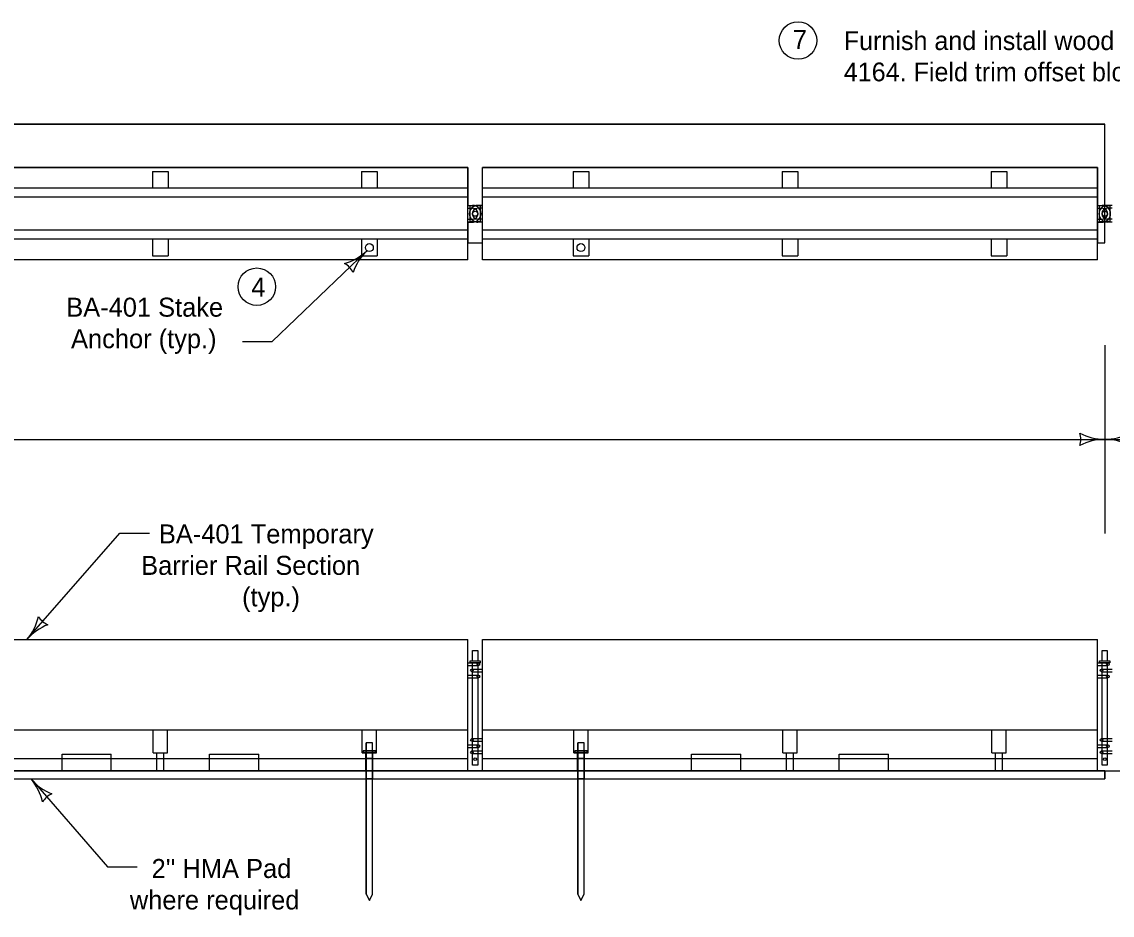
# Model space of a CAD drawing. Extents: x -2137026 to -2131464, y -2138478 to -2136524.
# Drawn here: x -2135538 to -2134666, y -2138230 to -2137516 of the extents above; entities that cross this region are included whole.
import ezdxf

# ---------------------------------------------------------------- set-up
doc = ezdxf.new("R2010")
doc.units = 0
for name, color, linetype in [('conPaving', 7, 'Continuous'), ('Level 2', 7, 'Continuous'), ('Level 3', 7, 'Continuous'), ('Level 41', 7, 'Continuous'), ('Level 9', 7, 'Continuous')]:
    doc.layers.add(name, color=color, linetype=linetype)

msp = doc.modelspace()

# ---------------------------------------------------------------- linework, layer by layer
at = {"layer": 'conPaving'}
for p, q in [((-2135592.12, -2138121.37), (-2135530.9, -2138121.37)), ((-2135530.9, -2138121.37), (-2135262.81, -2138121.37)), ((-2135348.82, -2138114.82), (-2135388.14, -2138114.82)), ((-2135262.81, -2138121.37), (-2135262.81, -2138114.82)), ((-2135257.89, -2138114.82), (-2135257.89, -2138121.37)), ((-2135257.89, -2138121.37), (-2135093.64, -2138121.37)), ((-2135093.64, -2138121.37), (-2135093.64, -2138114.82)), ((-2135088.73, -2138114.82), (-2135088.73, -2138121.37)), ((-2135088.73, -2138121.37), (-2134672.37, -2138121.37)), ((-2134884.74, -2138114.82), (-2134921.24, -2138114.82)), ((-2134672.37, -2138121.37), (-2134672.37, -2138114.82))]:
    msp.add_line(p, q, dxfattribs=at)
for points in [[(-2135430.3, -2138114.82), (-2135466.79, -2138114.82), (-2135506.11, -2138114.82), (-2135591.75, -2138114.82), (-2135592.12, -2138114.82)], [(-2135530.9, -2138121.37), (-2135530.9, -2138121.37)], [(-2135388.14, -2138114.82), (-2135424.63, -2138114.82), (-2135430.3, -2138114.82)], [(-2135262.81, -2138114.82), (-2135263.18, -2138114.82), (-2135348.82, -2138114.82)], [(-2135169.58, -2138114.82), (-2135181.95, -2138114.82), (-2135257.52, -2138114.82), (-2135257.89, -2138114.82)], [(-2135093.64, -2138114.82), (-2135094.01, -2138114.82), (-2135169.58, -2138114.82)], [(-2135002.71, -2138114.82), (-2135088.35, -2138114.82), (-2135088.73, -2138114.82)], [(-2134921.24, -2138114.82), (-2134926.9, -2138114.82), (-2134963.39, -2138114.82), (-2135002.71, -2138114.82)], [(-2134672.37, -2138114.82), (-2134678.55, -2138114.82), (-2134754.12, -2138114.82), (-2134759.78, -2138114.82), (-2134845.42, -2138114.82), (-2134884.74, -2138114.82)]]:
    msp.add_lwpolyline(points, dxfattribs=at)
msp.add_arc((-2135498.55, -2138093.81), 42.5, 220.43362, 220.43495, dxfattribs=at)
at = {"layer": 'Level 2'}
for p, q in [((-2135181.7, -2137632.29), (-2135673.22, -2137632.29)), ((-2135181.7, -2137706.01), (-2135181.7, -2137632.29)), ((-2134678.31, -2137632.29), (-2135169.83, -2137632.29)), ((-2135169.83, -2137706.01), (-2135169.83, -2137632.29)), ((-2134678.31, -2137706.01), (-2134678.31, -2137632.29)), ((-2135181.7, -2137648.67), (-2135673.22, -2137648.67)), ((-2134678.31, -2137648.67), (-2135169.83, -2137648.67)), ((-2135181.7, -2137656.04), (-2135673.22, -2137656.04)), ((-2134678.31, -2137656.04), (-2135169.83, -2137656.04)), ((-2135181.7, -2137682.26), (-2135673.22, -2137682.26)), ((-2134678.31, -2137682.26), (-2135169.83, -2137682.26)), ((-2135181.7, -2137689.63), (-2135673.22, -2137689.63)), ((-2134678.31, -2137689.63), (-2135169.83, -2137689.63)), ((-2135338.14, -2137771.44), (-2135262.36, -2137698.75)), ((-2135181.7, -2137706.01), (-2135673.22, -2137706.01)), ((-2134678.31, -2137706.01), (-2135169.83, -2137706.01)), ((-2135361.74, -2137771.44), (-2135338.14, -2137771.44)), ((-2134672.37, -2137774.34), (-2134672.37, -2137925.06)), ((-2135803.58, -2137849.7), (-2134672.37, -2137849.7)), ((-2134672.37, -2137849.7), (-2134532.49, -2137849.7)), ((-2135534.15, -2138009.96), (-2135459.86, -2137924.76)), ((-2135459.86, -2137924.76), (-2135436.26, -2137924.76)), ((-2135673.22, -2138009.96), (-2135181.7, -2138009.96)), ((-2135181.7, -2138114.57), (-2135181.7, -2138009.96)), ((-2135169.83, -2138114.57), (-2135169.83, -2138009.96)), ((-2135169.83, -2138009.96), (-2134678.31, -2138009.96)), ((-2134678.31, -2138114.57), (-2134678.31, -2138009.96)), ((-2135673.22, -2138082.05), (-2135181.7, -2138082.05)), ((-2135169.83, -2138082.05), (-2134678.31, -2138082.05)), ((-2135673.22, -2138104.99), (-2135181.7, -2138104.99)), ((-2135506.11, -2138101.71), (-2135466.79, -2138101.71)), ((-2135506.11, -2138114.82), (-2135506.11, -2138104.99)), ((-2135466.79, -2138114.82), (-2135466.79, -2138104.99)), ((-2135388.14, -2138101.71), (-2135348.82, -2138101.71)), ((-2135388.14, -2138114.82), (-2135388.14, -2138104.99)), ((-2135348.82, -2138114.82), (-2135348.82, -2138104.99)), ((-2135169.83, -2138104.99), (-2134678.31, -2138104.99)), ((-2135002.71, -2138101.71), (-2134963.39, -2138101.71)), ((-2135002.71, -2138114.82), (-2135002.71, -2138104.99)), ((-2134963.39, -2138114.82), (-2134963.39, -2138104.99)), ((-2134884.74, -2138101.71), (-2134845.42, -2138101.71)), ((-2134884.74, -2138114.82), (-2134884.74, -2138104.99)), ((-2134845.42, -2138114.82), (-2134845.42, -2138104.99)), ((-2135672.98, -2138114.82), (-2135506.11, -2138114.82)), ((-2135530.9, -2138121.37), (-2135469.67, -2138191.6)), ((-2135466.79, -2138114.82), (-2135388.14, -2138114.82)), ((-2135348.82, -2138114.82), (-2135181.95, -2138114.82)), ((-2135169.58, -2138114.82), (-2135002.71, -2138114.82)), ((-2134963.39, -2138114.82), (-2134884.74, -2138114.82)), ((-2134845.42, -2138114.82), (-2134678.55, -2138114.82)), ((-2135469.67, -2138191.6), (-2135446.07, -2138191.6))]:
    msp.add_line(p, q, dxfattribs=at)
for centre in [(-2134917.62, -2137530.59), (-2135350.36, -2137727.55)]:
    msp.add_circle(centre, 15, dxfattribs=at)
for centre, radius, start, end in [((-2135291.78, -2137668.08), 42.5, 285.73709, 313.80957), ((-2135232.94, -2137729.42), 42.5, 133.80957, 161.88206), ((-2135288.08, -2137723.42), 16.42, 26.07622, 61.54292), ((-2134708, -2137849.7), 16.42, 342.26665, 17.73335), ((-2134672.37, -2137807.2), 42.5, 241.92751, 270), ((-2134708, -2137849.7), 16.42, 342.26665, 17.73335), ((-2134672.37, -2137807.2), 42.5, 241.92751, 270), ((-2134672.37, -2137892.2), 42.5, 90, 118.07249), ((-2134672.37, -2137892.2), 42.5, 90, 118.07249), ((-2134672.37, -2137807.2), 42.5, 270, 298.07249), ((-2134672.37, -2137892.2), 42.5, 61.92751, 90), ((-2135566.5, -2137982.4), 42.5, 319.56638, 347.63887), ((-2135511.03, -2137982.84), 16.42, 211.83303, 247.29973), ((-2135501.8, -2138037.53), 42.5, 111.49389, 139.56638), ((-2135563.25, -2138148.94), 42.5, 12.36113, 40.43362), ((-2135498.55, -2138093.81), 42.5, 220.43362, 248.50611), ((-2135507.79, -2138148.5), 16.42, 112.70027, 148.16697)]:
    msp.add_arc(centre, radius, start, end, dxfattribs=at)
at = {"layer": 'Level 41'}
for p, q in [((-2135433.76, -2137635.41), (-2135421.17, -2137635.41)), ((-2135433.76, -2137635.41), (-2135433.76, -2137648.67)), ((-2135421.17, -2137635.41), (-2135421.17, -2137648.67)), ((-2135266.64, -2137635.41), (-2135266.64, -2137648.67)), ((-2135266.64, -2137635.41), (-2135254.06, -2137635.41)), ((-2135254.06, -2137635.41), (-2135254.06, -2137648.67)), ((-2135097.47, -2137635.41), (-2135084.89, -2137635.41)), ((-2135097.47, -2137635.41), (-2135097.47, -2137648.67)), ((-2135084.89, -2137635.41), (-2135084.89, -2137648.67)), ((-2134930.36, -2137635.41), (-2134917.77, -2137635.41)), ((-2134930.36, -2137635.41), (-2134930.36, -2137648.67)), ((-2134917.77, -2137635.41), (-2134917.77, -2137648.67)), ((-2134763.24, -2137635.41), (-2134763.24, -2137648.67)), ((-2134763.24, -2137635.41), (-2134750.66, -2137635.41)), ((-2134750.66, -2137635.41), (-2134750.66, -2137648.67)), ((-2135181.7, -2137662.47), (-2135177.77, -2137662.47)), ((-2135181.7, -2137664.82), (-2135177.77, -2137664.82)), ((-2135169.83, -2137662.47), (-2135173.76, -2137662.47)), ((-2135169.83, -2137664.82), (-2135173.76, -2137664.82)), ((-2134678.31, -2137662.47), (-2134674.37, -2137662.47)), ((-2134678.31, -2137664.82), (-2134674.37, -2137664.82)), ((-2134666.43, -2137662.47), (-2134670.36, -2137662.47)), ((-2134666.43, -2137664.82), (-2134670.36, -2137664.82)), ((-2135181.7, -2137673.48), (-2135177.77, -2137673.48)), ((-2135181.7, -2137675.83), (-2135177.77, -2137675.83)), ((-2135169.83, -2137673.48), (-2135173.76, -2137673.48)), ((-2135169.83, -2137675.83), (-2135173.76, -2137675.83)), ((-2134678.31, -2137673.48), (-2134674.37, -2137673.48)), ((-2134678.31, -2137675.83), (-2134674.37, -2137675.83)), ((-2134666.43, -2137673.48), (-2134670.36, -2137673.48)), ((-2134666.43, -2137675.83), (-2134670.36, -2137675.83)), ((-2135433.76, -2137689.63), (-2135433.76, -2137702.89)), ((-2135421.17, -2137689.63), (-2135421.17, -2137702.89)), ((-2135266.64, -2137689.63), (-2135266.64, -2137702.89)), ((-2135254.06, -2137689.63), (-2135254.06, -2137702.89)), ((-2135097.47, -2137689.63), (-2135097.47, -2137702.89)), ((-2135084.89, -2137689.63), (-2135084.89, -2137702.89)), ((-2134930.36, -2137689.63), (-2134930.36, -2137702.89)), ((-2134917.77, -2137689.63), (-2134917.77, -2137702.89)), ((-2134763.24, -2137689.63), (-2134763.24, -2137702.89)), ((-2134750.66, -2137689.63), (-2134750.66, -2137702.89)), ((-2135433.76, -2137702.89), (-2135421.17, -2137702.89)), ((-2135266.64, -2137702.89), (-2135254.06, -2137702.89)), ((-2135097.47, -2137702.89), (-2135084.89, -2137702.89)), ((-2134930.36, -2137702.89), (-2134917.77, -2137702.89)), ((-2134763.24, -2137702.89), (-2134750.66, -2137702.89)), ((-2135181.7, -2138028.56), (-2135173.2, -2138028.56)), ((-2135181.7, -2138030.68), (-2135173.2, -2138030.68)), ((-2135178.33, -2138033.48), (-2135169.83, -2138033.48)), ((-2135178.33, -2138035.6), (-2135169.83, -2138035.6)), ((-2134678.31, -2138028.56), (-2134669.8, -2138028.56)), ((-2134678.31, -2138030.68), (-2134669.8, -2138030.68)), ((-2134674.93, -2138033.48), (-2134666.43, -2138033.48)), ((-2134674.93, -2138035.6), (-2134666.43, -2138035.6)), ((-2135181.7, -2138038.39), (-2135173.2, -2138038.39)), ((-2135181.7, -2138040.51), (-2135173.2, -2138040.51)), ((-2134678.3, -2138038.39), (-2134669.8, -2138038.39)), ((-2134678.3, -2138040.51), (-2134669.8, -2138040.51)), ((-2135433.13, -2138100.62), (-2135433.13, -2138082.05)), ((-2135421.8, -2138100.62), (-2135421.8, -2138082.05)), ((-2135266.01, -2138100.62), (-2135266.01, -2138082.05)), ((-2135254.69, -2138100.62), (-2135254.69, -2138082.05)), ((-2135096.85, -2138100.62), (-2135096.85, -2138082.05)), ((-2135085.52, -2138100.62), (-2135085.52, -2138082.05)), ((-2134929.73, -2138100.62), (-2134929.73, -2138082.05)), ((-2134918.4, -2138100.62), (-2134918.4, -2138082.05)), ((-2134762.61, -2138100.62), (-2134762.61, -2138082.05)), ((-2134751.29, -2138100.62), (-2134751.29, -2138082.05)), ((-2135181.7, -2138094.1), (-2135173.21, -2138094.1)), ((-2135181.7, -2138096.22), (-2135173.21, -2138096.22)), ((-2135178.33, -2138089.18), (-2135169.83, -2138089.18)), ((-2135178.33, -2138091.31), (-2135169.83, -2138091.31)), ((-2134678.31, -2138094.1), (-2134669.81, -2138094.1)), ((-2134678.31, -2138096.22), (-2134669.81, -2138096.22)), ((-2134674.93, -2138089.18), (-2134666.44, -2138089.18)), ((-2134674.93, -2138091.31), (-2134666.44, -2138091.31)), ((-2135433.13, -2138100.62), (-2135421.8, -2138100.62)), ((-2135430.3, -2138114.82), (-2135430.3, -2138100.62)), ((-2135424.63, -2138114.82), (-2135424.63, -2138100.62)), ((-2135266.01, -2138100.62), (-2135254.69, -2138100.62)), ((-2135263.18, -2138114.82), (-2135263.18, -2138100.62)), ((-2135257.52, -2138114.82), (-2135257.52, -2138100.62)), ((-2135178.33, -2138099.01), (-2135169.83, -2138099.01)), ((-2135178.33, -2138101.14), (-2135169.83, -2138101.14)), ((-2135096.85, -2138100.62), (-2135085.52, -2138100.62)), ((-2135094.01, -2138114.82), (-2135094.01, -2138100.62)), ((-2135088.35, -2138114.82), (-2135088.35, -2138100.62)), ((-2134929.73, -2138100.62), (-2134918.4, -2138100.62)), ((-2134926.9, -2138114.82), (-2134926.9, -2138100.62)), ((-2134921.24, -2138114.82), (-2134921.24, -2138100.62)), ((-2134762.61, -2138100.62), (-2134751.29, -2138100.62)), ((-2134759.78, -2138114.82), (-2134759.78, -2138100.62)), ((-2134754.12, -2138114.82), (-2134754.12, -2138100.62)), ((-2134674.93, -2138099.01), (-2134666.44, -2138099.01)), ((-2134674.93, -2138101.14), (-2134666.44, -2138101.14))]:
    msp.add_line(p, q, dxfattribs=at)
for centre, radius in [((-2135260.35, -2137696.26), 3.15), ((-2135091.18, -2137696.26), 3.15), ((-2135178.33, -2138034.54), 1.06), ((-2135173.2, -2138029.62), 1.06), ((-2134674.93, -2138034.54), 1.06), ((-2134669.8, -2138029.62), 1.06), ((-2135173.2, -2138039.45), 1.06), ((-2134669.8, -2138039.45), 1.06), ((-2135178.33, -2138090.24), 1.06), ((-2135173.2, -2138095.16), 1.06), ((-2134674.93, -2138090.24), 1.06), ((-2134669.8, -2138095.16), 1.06), ((-2135178.33, -2138100.07), 1.06), ((-2134674.93, -2138100.07), 1.06)]:
    msp.add_circle(centre, radius, dxfattribs=at)
for centre, radius, start, end in [((-2135173.76, -2137669.15), 6.68, 90, 270), ((-2135173.76, -2137669.15), 4.33, 90, 270), ((-2135177.77, -2137669.15), 6.68, 270, 90), ((-2135177.77, -2137669.15), 4.33, 270, 90), ((-2134670.36, -2137669.15), 6.68, 90, 270), ((-2134670.36, -2137669.15), 4.33, 90, 270), ((-2134674.37, -2137669.15), 6.68, 270, 90), ((-2134674.37, -2137669.15), 4.33, 270, 90)]:
    msp.add_arc(centre, radius, start, end, dxfattribs=at)
at = {"layer": 'Level 9'}
for p, q in [((-2136691.9, -2137597.41), (-2134672.37, -2137597.41)), ((-2134672.37, -2137662.62), (-2134672.37, -2137597.41)), ((-2134672.37, -2137692.38), (-2134672.37, -2137597.41)), ((-2135673.22, -2137632.29), (-2135181.7, -2137632.29)), ((-2135169.83, -2137632.29), (-2134678.31, -2137632.29)), ((-2135181.7, -2137662.47), (-2135177.77, -2137662.47)), ((-2135179.86, -2137662.62), (-2135171.67, -2137662.62)), ((-2135179.86, -2137675.73), (-2135179.86, -2137662.62)), ((-2135176.34, -2137662.62), (-2135175.19, -2137662.62)), ((-2135173.76, -2137662.47), (-2135169.83, -2137662.47)), ((-2135171.67, -2137662.62), (-2135171.67, -2137675.73)), ((-2134678.31, -2137662.47), (-2134674.37, -2137662.47)), ((-2134676.46, -2137662.62), (-2134668.27, -2137662.62)), ((-2134676.46, -2137675.73), (-2134676.46, -2137662.62)), ((-2134672.94, -2137662.62), (-2134672.37, -2137662.62)), ((-2134668.27, -2137662.62), (-2134668.27, -2137675.73)), ((-2135177.77, -2137675.83), (-2135181.7, -2137675.83)), ((-2135171.67, -2137675.73), (-2135179.86, -2137675.73)), ((-2135174.95, -2137675.73), (-2135176.59, -2137675.73)), ((-2135169.83, -2137675.83), (-2135173.76, -2137675.83)), ((-2134674.37, -2137675.83), (-2134678.31, -2137675.83)), ((-2134668.27, -2137675.73), (-2134676.46, -2137675.73)), ((-2134672.37, -2137675.73), (-2134673.19, -2137675.73)), ((-2134672.37, -2137692.38), (-2134672.37, -2137675.73)), ((-2135181.7, -2137692.38), (-2135169.83, -2137692.38)), ((-2135181.7, -2137692.38), (-2135169.83, -2137692.38)), ((-2134678.31, -2137692.38), (-2134672.37, -2137692.38)), ((-2134678.31, -2137692.38), (-2134672.37, -2137692.38)), ((-2135179.86, -2138026.92), (-2135171.67, -2138026.92)), ((-2135179.86, -2138028.56), (-2135179.86, -2138026.92)), ((-2135177.81, -2138018.73), (-2135173.72, -2138018.73)), ((-2135177.81, -2138026.92), (-2135177.81, -2138018.73)), ((-2135173.72, -2138018.73), (-2135173.72, -2138026.92)), ((-2135171.67, -2138026.92), (-2135171.67, -2138028.56)), ((-2134676.46, -2138026.92), (-2134668.27, -2138026.92)), ((-2134676.46, -2138028.56), (-2134676.46, -2138026.92)), ((-2134674.42, -2138018.73), (-2134670.32, -2138018.73)), ((-2134674.42, -2138026.92), (-2134674.42, -2138018.73)), ((-2134670.32, -2138018.73), (-2134670.32, -2138026.92)), ((-2134668.27, -2138026.92), (-2134668.27, -2138028.56)), ((-2135171.67, -2138028.56), (-2135179.86, -2138028.56)), ((-2135177.81, -2138110.48), (-2135177.81, -2138028.56)), ((-2135173.72, -2138028.56), (-2135173.72, -2138110.48)), ((-2134668.27, -2138028.56), (-2134676.46, -2138028.56)), ((-2134674.42, -2138110.48), (-2134674.42, -2138028.56)), ((-2134670.32, -2138028.56), (-2134670.32, -2138110.48)), ((-2135257.89, -2138092.42), (-2135262.81, -2138092.42)), ((-2135262.81, -2138092.42), (-2135262.81, -2138098.98)), ((-2135257.89, -2138092.42), (-2135262.81, -2138092.42)), ((-2135262.81, -2138213.67), (-2135262.81, -2138092.42)), ((-2135257.89, -2138098.98), (-2135257.89, -2138092.42)), ((-2135257.89, -2138213.67), (-2135257.89, -2138092.42)), ((-2135088.73, -2138092.42), (-2135093.64, -2138092.42)), ((-2135093.64, -2138092.42), (-2135093.64, -2138098.98)), ((-2135088.73, -2138092.42), (-2135093.64, -2138092.42)), ((-2135093.64, -2138213.67), (-2135093.64, -2138092.42)), ((-2135088.73, -2138098.98), (-2135088.73, -2138092.42)), ((-2135088.73, -2138213.67), (-2135088.73, -2138092.42)), ((-2135506.11, -2138104.99), (-2135506.11, -2138101.71)), ((-2135506.11, -2138104.99), (-2135466.79, -2138104.99)), ((-2135466.79, -2138104.99), (-2135466.79, -2138101.71)), ((-2135388.14, -2138104.99), (-2135388.14, -2138101.71)), ((-2135388.14, -2138104.99), (-2135348.82, -2138104.99)), ((-2135348.82, -2138104.99), (-2135348.82, -2138101.71)), ((-2135265.26, -2138098.98), (-2135265.26, -2138100.62)), ((-2135262.81, -2138098.98), (-2135265.26, -2138098.98)), ((-2135265.26, -2138100.62), (-2135265.26, -2138098.98)), ((-2135265.26, -2138100.62), (-2135263.18, -2138100.62)), ((-2135263.18, -2138100.62), (-2135262.81, -2138100.62)), ((-2135257.89, -2138098.98), (-2135262.81, -2138098.98)), ((-2135262.81, -2138098.98), (-2135262.81, -2138100.62)), ((-2135262.81, -2138100.62), (-2135262.81, -2138098.98)), ((-2135262.81, -2138098.98), (-2135257.89, -2138098.98)), ((-2135257.89, -2138100.62), (-2135262.81, -2138100.62)), ((-2135262.81, -2138100.62), (-2135262.81, -2138104.99)), ((-2135262.81, -2138100.62), (-2135257.89, -2138100.62)), ((-2135257.89, -2138104.99), (-2135262.81, -2138104.99)), ((-2135262.81, -2138104.99), (-2135262.81, -2138114.82)), ((-2135262.81, -2138104.99), (-2135257.89, -2138104.99)), ((-2135257.89, -2138100.62), (-2135257.89, -2138098.98)), ((-2135257.89, -2138098.98), (-2135257.89, -2138100.62)), ((-2135257.89, -2138104.99), (-2135257.89, -2138100.62)), ((-2135257.89, -2138114.82), (-2135257.89, -2138104.99)), ((-2135096.1, -2138098.98), (-2135096.1, -2138100.62)), ((-2135093.64, -2138098.98), (-2135096.1, -2138098.98)), ((-2135096.1, -2138100.62), (-2135096.1, -2138098.98)), ((-2135096.1, -2138100.62), (-2135094.01, -2138100.62)), ((-2135094.01, -2138100.62), (-2135093.64, -2138100.62)), ((-2135088.73, -2138098.98), (-2135093.64, -2138098.98)), ((-2135093.64, -2138098.98), (-2135093.64, -2138100.62)), ((-2135093.64, -2138100.62), (-2135093.64, -2138098.98)), ((-2135093.64, -2138098.98), (-2135088.73, -2138098.98)), ((-2135088.73, -2138100.62), (-2135093.64, -2138100.62)), ((-2135093.64, -2138100.62), (-2135093.64, -2138104.99)), ((-2135093.64, -2138100.62), (-2135088.73, -2138100.62)), ((-2135088.73, -2138104.99), (-2135093.64, -2138104.99)), ((-2135093.64, -2138104.99), (-2135093.64, -2138114.82)), ((-2135093.64, -2138104.99), (-2135088.73, -2138104.99)), ((-2135088.73, -2138100.62), (-2135088.73, -2138098.98)), ((-2135088.73, -2138098.98), (-2135088.73, -2138100.62)), ((-2135088.73, -2138104.99), (-2135088.73, -2138100.62)), ((-2135088.73, -2138114.82), (-2135088.73, -2138104.99)), ((-2135002.71, -2138104.99), (-2135002.71, -2138101.71)), ((-2135002.71, -2138104.99), (-2134963.39, -2138104.99)), ((-2134963.39, -2138104.99), (-2134963.39, -2138101.71)), ((-2134884.74, -2138104.99), (-2134884.74, -2138101.71)), ((-2134884.74, -2138104.99), (-2134845.42, -2138104.99)), ((-2134845.42, -2138104.99), (-2134845.42, -2138101.71)), ((-2135173.72, -2138110.48), (-2135177.81, -2138110.48)), ((-2134670.32, -2138110.48), (-2134674.42, -2138110.48)), ((-2136987.54, -2138114.82), (-2134196.38, -2138114.82)), ((-2136691.9, -2138121.37), (-2134672.37, -2138121.37)), ((-2135257.89, -2138114.82), (-2135262.81, -2138114.82)), ((-2135262.81, -2138114.82), (-2135262.81, -2138121.37)), ((-2135262.81, -2138114.82), (-2135257.89, -2138114.82)), ((-2135257.89, -2138121.37), (-2135262.81, -2138121.37)), ((-2135262.81, -2138121.37), (-2135262.81, -2138213.67)), ((-2135262.81, -2138121.37), (-2135257.89, -2138121.37)), ((-2135257.89, -2138121.37), (-2135257.89, -2138114.82)), ((-2135257.89, -2138213.67), (-2135257.89, -2138121.37)), ((-2135181.95, -2138114.82), (-2135181.7, -2138114.57)), ((-2135169.83, -2138114.57), (-2135169.58, -2138114.82)), ((-2135088.73, -2138114.82), (-2135093.64, -2138114.82)), ((-2135093.64, -2138114.82), (-2135093.64, -2138121.37)), ((-2135093.64, -2138114.82), (-2135088.73, -2138114.82)), ((-2135088.73, -2138121.37), (-2135093.64, -2138121.37)), ((-2135093.64, -2138121.37), (-2135093.64, -2138213.67)), ((-2135093.64, -2138121.37), (-2135088.73, -2138121.37)), ((-2135088.73, -2138121.37), (-2135088.73, -2138114.82)), ((-2135088.73, -2138213.67), (-2135088.73, -2138121.37)), ((-2134678.55, -2138114.82), (-2134678.31, -2138114.57)), ((-2134672.37, -2138114.82), (-2134672.37, -2138121.37)), ((-2135262.81, -2138213.67), (-2135260.35, -2138218.58)), ((-2135262.81, -2138213.67), (-2135260.35, -2138218.58)), ((-2135260.35, -2138218.58), (-2135257.89, -2138213.67)), ((-2135260.35, -2138218.58), (-2135257.89, -2138213.67)), ((-2135093.64, -2138213.67), (-2135091.18, -2138218.58)), ((-2135093.64, -2138213.67), (-2135091.18, -2138218.58)), ((-2135091.18, -2138218.58), (-2135088.73, -2138213.67)), ((-2135091.18, -2138218.58), (-2135088.73, -2138213.67))]:
    msp.add_line(p, q, dxfattribs=at)
for points in [[(-2134672.37, -2137597.41), (-2136006.53, -2137597.41), (-2136191.5, -2137597.41), (-2136191.5, -2137597.41)], [(-2135181.7, -2137632.29), (-2135181.7, -2137648.67), (-2135181.7, -2137656.04), (-2135181.7, -2137662.47)], [(-2135169.83, -2137662.47), (-2135169.83, -2137656.04), (-2135169.83, -2137648.67), (-2135169.83, -2137632.29)], [(-2134678.31, -2137632.29), (-2134678.31, -2137648.67), (-2134678.31, -2137656.04), (-2134678.31, -2137662.47)], [(-2135181.7, -2137675.83), (-2135181.7, -2137682.26), (-2135181.7, -2137689.63), (-2135181.7, -2137692.38)], [(-2135169.83, -2137692.38), (-2135169.83, -2137689.63), (-2135169.83, -2137682.26), (-2135169.83, -2137675.83)], [(-2134678.31, -2137675.83), (-2134678.31, -2137682.26), (-2134678.31, -2137689.63), (-2134678.31, -2137692.38)], [(-2135265.26, -2138098.98), (-2135255.43, -2138098.98), (-2135255.43, -2138100.62), (-2135265.26, -2138100.62)], [(-2135255.43, -2138100.62), (-2135255.43, -2138098.98), (-2135257.89, -2138098.98)], [(-2135257.89, -2138100.62), (-2135257.52, -2138100.62), (-2135255.43, -2138100.62)], [(-2135096.1, -2138098.98), (-2135086.27, -2138098.98), (-2135086.27, -2138100.62), (-2135096.1, -2138100.62)], [(-2135086.27, -2138100.62), (-2135086.27, -2138098.98), (-2135088.73, -2138098.98)], [(-2135088.73, -2138100.62), (-2135088.35, -2138100.62), (-2135086.27, -2138100.62)]]:
    msp.add_lwpolyline(points, dxfattribs=at)
for centre, radius in [((-2135175.77, -2137669.17), 2.05), ((-2134672.37, -2137669.17), 2.05), ((-2135175.77, -2138105.57), 1.02), ((-2134672.37, -2138105.57), 1.02)]:
    msp.add_circle(centre, radius, dxfattribs=at)
for centre, start, end in [((-2135177.77, -2137669.15), 77.60428, 90), ((-2135173.76, -2137669.15), 90, 102.39572), ((-2134674.37, -2137669.15), 77.60428, 90), ((-2135177.77, -2137669.15), 270, 280.2309), ((-2135173.76, -2137669.15), 259.7691, 270), ((-2134674.37, -2137669.15), 270, 280.2309)]:
    msp.add_arc(centre, 6.68, start, end, dxfattribs=at)

# ---------------------------------------------------------------- texts
at = {"layer": 'Level 2'}
for s, p in [('7', (-2134921.84, -2137537.43)), ('4', (-2135354.73, -2137735.45))]:
    msp.add_text(s, height=15.2, dxfattribs=at).set_placement(p)
at = {"layer": 'Level 3'}
for s, p in [('BA-401 Stake', (-2135502.71, -2137751.54)), ('Anchor (typ.)', (-2135498.88, -2137776.74)), ('BA-401 Temporary', (-2135428.65, -2137932.92)), ('Barrier Rail Section', (-2135442.82, -2137958.12)), ('(typ.)', (-2135362.13, -2137983.32)), ("2'' HMA Pad", (-2135434.48, -2138200.65)), ('where required', (-2135451.87, -2138225.85))]:
    msp.add_text(s, height=15.2, dxfattribs=at).set_placement(p)
at = {"layer": 'Level 9'}
for s, p in [('Furnish and install wood offset blocks meeting the requirements of Section ', (-2134881.04, -2137538.19)), ('4164. Field trim offset blocks as required for proper fit.', (-2134881.04, -2137563.19))]:
    msp.add_text(s, height=15, dxfattribs=at).set_placement(p)

doc.saveas('drawing.dxf')
